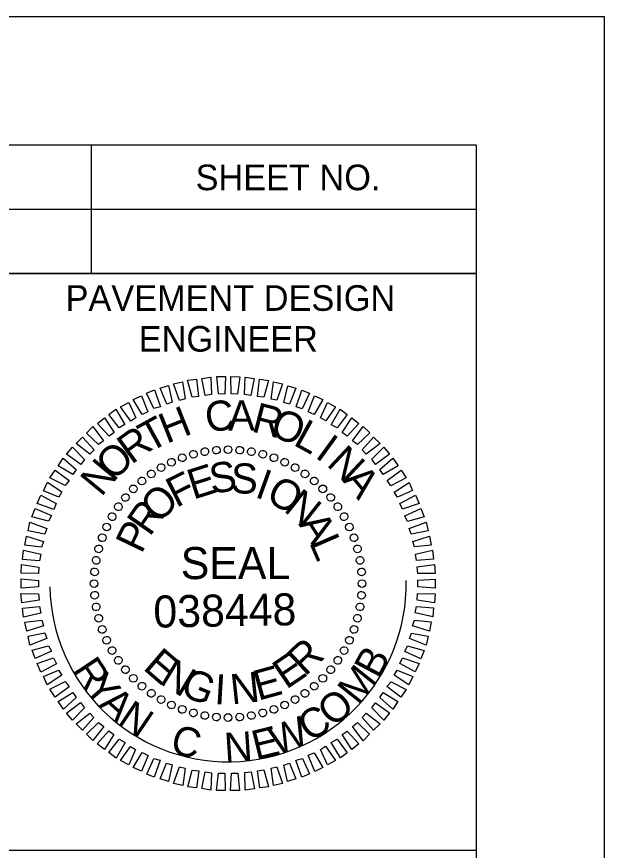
# Model space of a CAD drawing. Extents: x 573078 to 573143.6, y -55221.3 to -55199.3.
# Drawn here: x 573109.723 to 573112.014, y -55202.55 to -55199.298 of the extents above; entities that cross this region are included whole.
import ezdxf

# ---------------------------------------------------------------- set-up
doc = ezdxf.new("R2010")
doc.units = 0
for name, color, linetype in [('Scratch_Level_0', 7, 'Continuous'), ('Scratch_Level_1', 7, 'Continuous'), ('Sheet Plan CELL', 7, 'Continuous'), ('Sheet Plot Border Inside CELL', 7, 'Continuous'), ('Sheet Professional Seal CELL', 7, 'Continuous')]:
    doc.layers.add(name, color=color, linetype=linetype)

msp = doc.modelspace()

# ---------------------------------------------------------------- linework, layer by layer
at = {"layer": 'Scratch_Level_0'}
msp.add_arc((573110.547, -55201.5095), 0.6949, 181, 1, dxfattribs=at)
at = {"layer": 'Scratch_Level_1'}
msp.add_line((573110.547, -55201.5095), (573110.547, -55201.5095), dxfattribs=at)
at = {"layer": 'Sheet Plan CELL'}
for p, q in [((573110.0144, -55200.2999), (573110.0144, -55199.7984)), ((573107.5132, -55200.0494), (573111.5142, -55200.0497))]:
    msp.add_line(p, q, dxfattribs=at)
for points in [[(573081.5142, -55199.7984), (573111.5142, -55199.7984), (573111.5142, -55220.7984), (573081.5142, -55220.7984)], [(573107.5132, -55199.7984), (573111.5142, -55199.7984), (573111.5142, -55200.3002), (573107.5132, -55200.3002)], [(573109.5142, -55200.3002), (573111.5142, -55200.3002), (573111.5142, -55202.5502), (573109.5142, -55202.5502)]]:
    msp.add_lwpolyline(points, close=True, dxfattribs=at)
at = {"layer": 'Sheet Plot Border Inside CELL'}
msp.add_lwpolyline([(573112.0142, -55199.2984), (573078.0142, -55199.2984), (573078.0142, -55221.2984), (573112.0142, -55221.2984)], close=True, dxfattribs=at)
at = {"layer": 'Sheet Professional Seal CELL'}
for p, q in [((573110.4568, -55200.9954), (573110.4568, -55200.9954)), ((573110.5015, -55200.9884), (573110.5015, -55200.9884)), ((573110.5473, -55200.9866), (573110.5473, -55200.9866)), ((573110.5931, -55200.9889), (573110.5931, -55200.9889)), ((573110.638, -55200.9954), (573110.638, -55200.9954)), ((573110.3676, -55201.0178), (573110.3676, -55201.0178)), ((573110.4111, -55201.0046), (573110.4111, -55201.0046)), ((573110.6819, -55201.004), (573110.6819, -55201.004)), ((573110.7259, -55201.0178), (573110.7259, -55201.0178)), ((573110.286, -55201.0568), (573110.286, -55201.0568)), ((573110.3262, -55201.0352), (573110.3262, -55201.0352)), ((573110.7679, -55201.0358), (573110.7679, -55201.0358)), ((573110.8089, -55201.056), (573110.8089, -55201.056)), ((573110.2468, -55201.0814), (573110.2468, -55201.0814)), ((573110.8468, -55201.0813), (573110.8468, -55201.0813)), ((573110.2109, -55201.1081), (573110.2109, -55201.1081)), ((573110.8837, -55201.1088), (573110.8837, -55201.1088)), ((573110.177, -55201.1399), (573110.177, -55201.1399)), ((573110.9166, -55201.1395), (573110.9166, -55201.1395)), ((573110.1464, -55201.1727), (573110.1464, -55201.1727)), ((573110.9484, -55201.1733), (573110.9484, -55201.1733)), ((573110.1189, -55201.2097), (573110.1189, -55201.2097)), ((573110.9751, -55201.2093), (573110.9751, -55201.2093)), ((573110.0935, -55201.2476), (573110.0935, -55201.2476)), ((573110.9997, -55201.2485), (573110.9997, -55201.2485)), ((573110.0734, -55201.2886), (573110.0734, -55201.2886)), ((573111.0212, -55201.2887), (573111.0212, -55201.2887)), ((573110.0554, -55201.3306), (573110.0554, -55201.3306)), ((573111.0386, -55201.3301), (573111.0386, -55201.3301)), ((573110.0416, -55201.3745), (573110.0416, -55201.3745)), ((573111.0519, -55201.3736), (573111.0519, -55201.3736)), ((573110.033, -55201.4184), (573110.033, -55201.4184)), ((573111.061, -55201.4192), (573111.061, -55201.4192)), ((573110.0264, -55201.4633), (573110.0264, -55201.4633)), ((573111.068, -55201.4639), (573111.068, -55201.4639)), ((573110.0241, -55201.5092), (573110.0241, -55201.5092)), ((573110.547, -55201.5095), (573110.547, -55201.5095)), ((573111.0699, -55201.5097), (573111.0699, -55201.5097)), ((573110.026, -55201.555), (573110.026, -55201.555)), ((573111.0676, -55201.5556), (573111.0676, -55201.5556)), ((573110.033, -55201.5997), (573110.033, -55201.5997)), ((573111.0611, -55201.6005), (573111.0611, -55201.6005)), ((573110.0421, -55201.6453), (573110.0421, -55201.6453)), ((573111.0524, -55201.6444), (573111.0524, -55201.6444)), ((573110.0554, -55201.6889), (573110.0554, -55201.6889)), ((573111.0386, -55201.6884), (573111.0386, -55201.6884)), ((573110.0728, -55201.7302), (573110.0728, -55201.7302)), ((573111.0206, -55201.7303), (573111.0206, -55201.7303)), ((573110.0943, -55201.7705), (573110.0943, -55201.7705)), ((573111.0005, -55201.7713), (573111.0005, -55201.7713)), ((573110.1189, -55201.8096), (573110.1189, -55201.8096)), ((573110.9751, -55201.8093), (573110.9751, -55201.8093)), ((573110.1456, -55201.8456), (573110.1456, -55201.8456)), ((573110.9476, -55201.8462), (573110.9476, -55201.8462)), ((573110.1775, -55201.8794), (573110.1775, -55201.8794)), ((573110.917, -55201.879), (573110.917, -55201.879)), ((573110.2103, -55201.9101), (573110.2103, -55201.9101)), ((573110.2472, -55201.9376), (573110.2472, -55201.9376)), ((573110.8472, -55201.9375), (573110.8472, -55201.9375)), ((573110.8832, -55201.9109), (573110.8832, -55201.9109)), ((573110.2852, -55201.963), (573110.2852, -55201.963)), ((573110.808, -55201.9622), (573110.808, -55201.9622)), ((573110.3261, -55201.9831), (573110.3261, -55201.9831)), ((573110.3681, -55202.0011), (573110.3681, -55202.0011)), ((573110.7264, -55202.0011), (573110.7264, -55202.0011)), ((573110.7678, -55201.9837), (573110.7678, -55201.9837)), ((573110.4121, -55202.0149), (573110.4121, -55202.0149)), ((573110.456, -55202.0235), (573110.456, -55202.0235)), ((573110.5009, -55202.03), (573110.5009, -55202.03)), ((573110.5468, -55202.0323), (573110.5468, -55202.0323)), ((573110.5926, -55202.0305), (573110.5926, -55202.0305)), ((573110.6372, -55202.0235), (573110.6372, -55202.0235)), ((573110.6829, -55202.0143), (573110.6829, -55202.0143))]:
    msp.add_line(p, q, dxfattribs=at)
for points in [[(573110.4571, -55200.7757), (573110.4445, -55200.7092), (573110.4798, -55200.7044), (573110.4821, -55200.7721)], [(573110.5091, -55200.7696), (573110.5027, -55200.702), (573110.5371, -55200.7024), (573110.5341, -55200.7702)], [(573110.5591, -55200.7697), (573110.5579, -55200.702), (573110.5923, -55200.7025), (573110.5841, -55200.7703)], [(573110.6112, -55200.7719), (573110.6142, -55200.7042), (573110.6487, -55200.7098), (573110.6363, -55200.7757)], [(573110.3077, -55200.8095), (573110.2827, -55200.7475), (573110.3148, -55200.7375), (573110.3295, -55200.8019)], [(573110.3575, -55200.7951), (573110.3345, -55200.7299), (573110.3697, -55200.722), (573110.3792, -55200.7895)], [(573110.4072, -55200.7828), (573110.3894, -55200.7164), (573110.4237, -55200.7127), (573110.4322, -55200.7792)], [(573110.6613, -55200.7794), (573110.6695, -55200.7126), (573110.704, -55200.7172), (573110.6864, -55200.7821)], [(573110.7146, -55200.7899), (573110.7239, -55200.7221), (573110.7594, -55200.7298), (573110.7366, -55200.7947)], [(573110.7649, -55200.8026), (573110.7794, -55200.7378), (573110.8118, -55200.7476), (573110.7869, -55200.8095)], [(573110.257, -55200.8271), (573110.2289, -55200.7672), (573110.2599, -55200.7541), (573110.2829, -55200.8204)], [(573110.812, -55200.8205), (573110.8348, -55200.7545), (573110.8642, -55200.7665), (573110.8361, -55200.8274)], [(573110.1672, -55200.8755), (573110.1277, -55200.82), (573110.1597, -55200.8027), (573110.1868, -55200.8627)], [(573110.2116, -55200.8497), (573110.1772, -55200.792), (573110.2092, -55200.7769), (573110.2343, -55200.84)], [(573110.8592, -55200.8395), (573110.8842, -55200.7776), (573110.9167, -55200.7916), (573110.8824, -55200.8505)], [(573110.9076, -55200.8626), (573110.9346, -55200.8027), (573110.9662, -55200.8199), (573110.9276, -55200.8747)], [(573110.1219, -55200.9023), (573110.0824, -55200.8499), (573110.1091, -55200.8297), (573110.1445, -55200.8894)], [(573110.9487, -55200.89), (573110.9841, -55200.829), (573111.0115, -55200.8504), (573110.9718, -55200.9021)], [(573110.0828, -55200.9343), (573110.0372, -55200.8851), (573110.0649, -55200.8627), (573110.1024, -55200.9204)], [(573110.9919, -55200.9205), (573111.0294, -55200.8625), (573111.0569, -55200.885), (573111.0119, -55200.9347)], [(573110.0417, -55200.9673), (573109.9951, -55200.9223), (573110.0197, -55200.8968), (573110.0613, -55200.9524)], [(573111.032, -55200.9521), (573111.0738, -55200.8972), (573111.0992, -55200.9217), (573111.0521, -55200.9674)], [(573110.008, -55201.0043), (573109.9542, -55200.9626), (573109.9798, -55200.9382), (573110.0244, -55200.9874)], [(573111.0702, -55200.9879), (573111.1141, -55200.9381), (573111.1395, -55200.9627), (573111.0861, -55201.0043)], [(573109.9723, -55201.0445), (573109.9174, -55201.0049), (573109.9398, -55200.9774), (573109.9865, -55201.0255)], [(573111.1073, -55201.0247), (573111.1543, -55200.977), (573111.1767, -55201.0048), (573111.1222, -55201.0453)], [(573109.9417, -55201.0846), (573109.8849, -55201.0502), (573109.9041, -55201.0197), (573109.9549, -55201.0646)], [(573111.1392, -55201.0648), (573111.1895, -55201.0202), (573111.2098, -55201.05), (573111.152, -55201.0843)], [(573109.9112, -55201.1268), (573109.8524, -55201.0966), (573109.8727, -55201.0671), (573109.9275, -55201.1078)], [(573111.167, -55201.107), (573111.2215, -55201.0665), (573111.2418, -55201.0974), (573111.182, -55201.1276)], [(573109.887, -55201.172), (573109.8272, -55201.1471), (573109.8422, -55201.1145), (573109.8991, -55201.152)], [(573111.1949, -55201.1523), (573111.2526, -55201.1149), (573111.2667, -55201.1469), (573111.2077, -55201.1719)], [(573109.867, -55201.2203), (573109.802, -55201.1975), (573109.8171, -55201.1649), (573109.877, -55201.1972)], [(573111.2165, -55201.1968), (573111.2774, -55201.1644), (573111.2915, -55201.1975), (573111.2273, -55201.2195)], [(573109.847, -55201.2665), (573109.7821, -55201.2489), (573109.7951, -55201.2164), (573109.8581, -55201.2444)], [(573111.2361, -55201.2454), (573111.2991, -55201.2172), (573111.3112, -55201.2493), (573111.2469, -55201.2671)], [(573109.8322, -55201.3167), (573109.7674, -55201.3043), (573109.7741, -55201.2698), (573109.8402, -55201.2947)], [(573111.2536, -55201.2951), (573111.3198, -55201.2699), (573111.3267, -55201.3042), (573111.2613, -55201.3168)], [(573109.8196, -55201.367), (573109.7549, -55201.3598), (573109.7615, -55201.3242), (573109.8275, -55201.3449)], [(573111.267, -55201.3448), (573111.3322, -55201.3239), (573111.3391, -55201.3592), (573111.2736, -55201.3666)], [(573109.8122, -55201.4202), (573109.7454, -55201.4151), (573109.749, -55201.3797), (573109.8169, -55201.3951)], [(573111.2772, -55201.3946), (573111.3447, -55201.3789), (573111.3484, -55201.4142), (573111.2818, -55201.4196)], [(573109.8078, -55201.4703), (573109.7401, -55201.4694), (573109.7416, -55201.435), (573109.8095, -55201.4453)], [(573111.2844, -55201.4445), (573111.3519, -55201.435), (573111.3546, -55201.4704), (573111.2869, -55201.4695)], [(573109.8077, -55201.5224), (573109.7401, -55201.5267), (573109.7395, -55201.4913), (573109.8073, -55201.4974)], [(573111.2863, -55201.4966), (573111.3539, -55201.4922), (573111.3546, -55201.5277), (573111.2867, -55201.5215)], [(573109.8097, -55201.5744), (573109.7421, -55201.5839), (573109.7394, -55201.5486), (573109.8071, -55201.5495)], [(573111.2862, -55201.5486), (573111.3539, -55201.5495), (573111.3524, -55201.5839), (573111.2845, -55201.5737)], [(573109.8168, -55201.6243), (573109.7493, -55201.64), (573109.7456, -55201.6047), (573109.8122, -55201.5994)], [(573111.2818, -55201.5987), (573111.3486, -55201.6038), (573111.345, -55201.6393), (573111.2771, -55201.6238)], [(573109.827, -55201.6741), (573109.7618, -55201.695), (573109.7549, -55201.6597), (573109.8204, -55201.6523)], [(573111.2744, -55201.652), (573111.3391, -55201.6592), (573111.3325, -55201.6947), (573111.2665, -55201.674)], [(573109.8404, -55201.7239), (573109.7742, -55201.749), (573109.7673, -55201.7147), (573109.8327, -55201.7021)], [(573111.2618, -55201.7022), (573111.3266, -55201.7146), (573111.3199, -55201.7491), (573111.2538, -55201.7242)], [(573109.8579, -55201.7736), (573109.7949, -55201.8017), (573109.7829, -55201.7697), (573109.8471, -55201.7519)], [(573111.247, -55201.7524), (573111.3119, -55201.77), (573111.2989, -55201.8026), (573111.236, -55201.7745)], [(573109.8775, -55201.8222), (573109.8166, -55201.8545), (573109.8025, -55201.8214), (573109.8667, -55201.7994)], [(573111.227, -55201.7986), (573111.292, -55201.8214), (573111.2769, -55201.854), (573111.217, -55201.8217)], [(573109.8991, -55201.8666), (573109.8414, -55201.904), (573109.8273, -55201.872), (573109.8863, -55201.847)], [(573111.207, -55201.8469), (573111.2668, -55201.8719), (573111.2518, -55201.9044), (573111.1949, -55201.8669)], [(573109.927, -55201.9119), (573109.8725, -55201.9525), (573109.8522, -55201.9216), (573109.9121, -55201.8913)], [(573111.1828, -55201.8921), (573111.2417, -55201.9223), (573111.2213, -55201.9518), (573111.1665, -55201.9111)], [(573109.9548, -55201.9541), (573109.9046, -55201.9988), (573109.8842, -55201.9689), (573109.942, -55201.9346)], [(573111.1523, -55201.9343), (573111.2091, -55201.9687), (573111.1899, -55201.9992), (573111.1391, -55201.9543)], [(573109.9868, -55201.9942), (573109.9397, -55202.0419), (573109.9173, -55202.0142), (573109.9718, -55201.9736)], [(573111.1217, -55201.9744), (573111.1766, -55202.0141), (573111.1542, -55202.0415), (573111.1075, -55201.9934)], [(573110.0239, -55202.0311), (573109.9799, -55202.0808), (573109.9545, -55202.0562), (573110.0079, -55202.0147)], [(573111.086, -55202.0146), (573111.1398, -55202.0564), (573111.1142, -55202.0808), (573111.0696, -55202.0315)], [(573110.062, -55202.0668), (573110.0202, -55202.1217), (573109.9948, -55202.0972), (573110.0419, -55202.0516)], [(573111.0523, -55202.0516), (573111.0989, -55202.0967), (573111.0743, -55202.1221), (573111.0327, -55202.0666)], [(573110.1021, -55202.0984), (573110.0646, -55202.1564), (573110.0371, -55202.1339), (573110.0821, -55202.0842)], [(573111.0112, -55202.0846), (573111.0568, -55202.1338), (573111.0291, -55202.1562), (573110.9916, -55202.0985)], [(573110.1454, -55202.1289), (573110.11, -55202.19), (573110.0825, -55202.1686), (573110.1222, -55202.1168)], [(573110.9722, -55202.1166), (573111.0116, -55202.169), (573110.9849, -55202.1893), (573110.9495, -55202.1295)], [(573110.1865, -55202.1563), (573110.1594, -55202.2162), (573110.1278, -55202.199), (573110.1664, -55202.1442)], [(573110.2348, -55202.1794), (573110.2098, -55202.2413), (573110.1773, -55202.2273), (573110.2117, -55202.1684)], [(573110.8825, -55202.1692), (573110.9168, -55202.2269), (573110.8848, -55202.242), (573110.8597, -55202.1789)], [(573110.9268, -55202.1434), (573110.9663, -55202.199), (573110.9343, -55202.2162), (573110.9072, -55202.1562)], [(573110.282, -55202.1984), (573110.2592, -55202.2644), (573110.2298, -55202.2524), (573110.2579, -55202.1915)], [(573110.837, -55202.1918), (573110.8651, -55202.2518), (573110.8341, -55202.2648), (573110.8111, -55202.1985)], [(573110.3292, -55202.2163), (573110.3147, -55202.2812), (573110.2822, -55202.2713), (573110.3072, -55202.2094)], [(573110.3794, -55202.229), (573110.3701, -55202.2969), (573110.3346, -55202.2891), (573110.3574, -55202.2242)], [(573110.7365, -55202.2238), (573110.7596, -55202.289), (573110.7243, -55202.2969), (573110.7148, -55202.2294)], [(573110.7863, -55202.2094), (573110.8113, -55202.2715), (573110.7792, -55202.2814), (573110.7645, -55202.2171)], [(573110.4327, -55202.2395), (573110.4245, -55202.3063), (573110.39, -55202.3017), (573110.4076, -55202.2368)], [(573110.4828, -55202.247), (573110.4798, -55202.3147), (573110.4453, -55202.3091), (573110.4577, -55202.2433)], [(573110.5349, -55202.2492), (573110.5361, -55202.3169), (573110.5017, -55202.3164), (573110.5099, -55202.2486)], [(573110.5849, -55202.2494), (573110.5913, -55202.317), (573110.5569, -55202.3165), (573110.5599, -55202.2488)], [(573110.6369, -55202.2433), (573110.6495, -55202.3097), (573110.6142, -55202.3145), (573110.612, -55202.2468)], [(573110.6868, -55202.2361), (573110.7046, -55202.3025), (573110.6703, -55202.3062), (573110.6618, -55202.2397)]]:
    msp.add_lwpolyline(points, close=True, dxfattribs=at)
for centre, major_axis in [((573110.4118, -55201.0049), (-0.0039, 0.0145)), ((573110.4563, -55200.995), (-0.0026, 0.0148)), ((573110.5015, -55200.9891), (-0.0013, 0.0149)), ((573110.547, -55200.9871), (0, 0.015)), ((573110.5925, -55200.9891), (0.0013, 0.0149)), ((573110.6377, -55200.995), (0.0026, 0.0148)), ((573110.6822, -55201.0049), (0.0039, 0.0145)), ((573110.3262, -55201.036), (-0.0063, 0.0136)), ((573110.3683, -55201.0186), (-0.0051, 0.0141)), ((573110.7257, -55201.0186), (0.0051, 0.0141)), ((573110.7678, -55201.036), (0.0063, 0.0136)), ((573110.2858, -55201.0571), (-0.0075, 0.013)), ((573110.8082, -55201.0571), (0.0075, 0.013)), ((573110.2112, -55201.1093), (-0.0096, 0.0115)), ((573110.2474, -55201.0816), (-0.0086, 0.0123)), ((573110.8466, -55201.0816), (0.0086, 0.0123)), ((573110.8828, -55201.1093), (0.0096, 0.0115)), ((573110.1776, -55201.1401), (-0.0106, 0.0106)), ((573110.9164, -55201.1401), (0.0106, 0.0106)), ((573110.1468, -55201.1737), (-0.0115, 0.0096)), ((573110.9472, -55201.1737), (0.0115, 0.0096)), ((573110.1191, -55201.2098), (-0.0123, 0.0086)), ((573110.9749, -55201.2098), (0.0123, 0.0086)), ((573110.0946, -55201.2483), (-0.013, 0.0075)), ((573110.9994, -55201.2483), (0.013, 0.0075)), ((573110.0736, -55201.2887), (-0.0136, 0.0063)), ((573111.0204, -55201.2887), (0.0136, 0.0063)), ((573110.0561, -55201.3308), (-0.0141, 0.0051)), ((573111.0379, -55201.3308), (0.0141, 0.0051)), ((573110.0424, -55201.3743), (-0.0145, 0.0039)), ((573111.0516, -55201.3743), (0.0145, 0.0039)), ((573110.0326, -55201.4187), (-0.0148, 0.0026)), ((573111.0615, -55201.4187), (0.0148, 0.0026)), ((573110.0266, -55201.4639), (-0.0149, 0.0013)), ((573111.0674, -55201.4639), (0.0149, 0.0013)), ((573110.0246, -55201.5095), (-0.015, 0)), ((573111.0694, -55201.5095), (0.015, 0)), ((573110.0266, -55201.555), (-0.0149, -0.0013)), ((573111.0674, -55201.555), (0.0149, -0.0013)), ((573110.0326, -55201.6002), (-0.0148, -0.0026)), ((573111.0615, -55201.6002), (0.0148, -0.0026)), ((573110.0424, -55201.6447), (-0.0145, -0.0039)), ((573111.0516, -55201.6447), (0.0145, -0.0039)), ((573110.0561, -55201.6881), (-0.0141, -0.0051)), ((573111.0379, -55201.6881), (0.0141, -0.0051)), ((573110.0736, -55201.7302), (-0.0136, -0.0063)), ((573111.0204, -55201.7302), (0.0136, -0.0063)), ((573110.0946, -55201.7706), (-0.013, -0.0075)), ((573110.9994, -55201.7706), (0.013, -0.0075)), ((573110.1191, -55201.8091), (-0.0123, -0.0086)), ((573110.9749, -55201.8091), (0.0123, -0.0086)), ((573110.1468, -55201.8452), (-0.0115, -0.0096)), ((573110.9472, -55201.8452), (0.0115, -0.0096)), ((573110.1776, -55201.8788), (-0.0106, -0.0106)), ((573110.9164, -55201.8788), (0.0106, -0.0106)), ((573110.2112, -55201.9096), (-0.0096, -0.0115)), ((573110.8828, -55201.9096), (0.0096, -0.0115)), ((573110.2474, -55201.9374), (-0.0086, -0.0123)), ((573110.8466, -55201.9374), (0.0086, -0.0123)), ((573110.2858, -55201.9619), (-0.0075, -0.013)), ((573110.3262, -55201.9829), (-0.0063, -0.0136)), ((573110.7678, -55201.9829), (0.0063, -0.0136)), ((573110.8082, -55201.9619), (0.0075, -0.013)), ((573110.3683, -55202.0003), (-0.0051, -0.0141)), ((573110.4118, -55202.014), (-0.0039, -0.0145)), ((573110.6822, -55202.014), (0.0039, -0.0145)), ((573110.7257, -55202.0003), (0.0051, -0.0141)), ((573110.4563, -55202.0239), (-0.0026, -0.0148)), ((573110.5015, -55202.0299), (-0.0013, -0.0149)), ((573110.547, -55202.0318), (0, -0.015)), ((573110.5925, -55202.0299), (0.0013, -0.0149)), ((573110.6377, -55202.0239), (0.0026, -0.0148))]:
    msp.add_ellipse(centre, major_axis=major_axis, ratio=0.999708, dxfattribs=at)

# ---------------------------------------------------------------- texts
at = {"layer": 'Sheet Plan CELL'}
for s, height, p in [('SHEET NO.', 0.1, (573110.4204, -55199.9752)), ('PAVEMENT DESIGN', 0.100002, (573109.9133, -55200.4457)), ('ENGINEER', 0.1, (573110.1987, -55200.6049))]:
    msp.add_text(s, height=height, rotation=0, dxfattribs=at).set_placement(p)
at = {"layer": 'Sheet Professional Seal CELL'}
for s, height, rotation, p in [('C', 0.1174, 7.2199, (573110.4649, -55200.9203)), ('A', 0.1174, 0.0203, (573110.547, -55200.9126)), ('H', 0.1174, 21.6195, (573110.3073, -55200.9647)), ('R', 0.1174, 345.6211, (573110.6345, -55200.9153)), ('O', 0.1174, 338.4212, (573110.7046, -55200.9297)), ('T', 0.1174, 28.8198, (573110.2402, -55201.0003)), ('L', 0.1174, 331.2209, (573110.7969, -55200.9666)), ('R', 0.1174, 36.0205, (573110.1702, -55201.0473)), ('I', 0.1174, 324.0201, (573110.8821, -55201.0151)), ('O', 0.1174, 43.2217, (573110.0995, -55201.1131)), ('N', 0.1174, 316.8189, (573110.9274, -55201.0466)), ('N', 0.1174, 50.4235, (573110.0527, -55201.1744)), ('S', 0.1174, 8.2556, (573110.4826, -55201.1596)), ('E', 0.1174, 17.6111, (573110.4111, -55201.1827)), ('S', 0.1174, 358.9004, (573110.5575, -55201.1572)), ('F', 0.1174, 26.967, (573110.345, -55201.2151)), ('I', 0.1174, 340.1896, (573110.6473, -55201.1702)), ('A', 0.1174, 309.6172, (573110.9899, -55201.107)), ('O', 0.1174, 330.8335, (573110.6892, -55201.1841)), ('O', 0.1174, 45.6812, (573110.2774, -55201.2777)), ('N', 0.1174, 321.4766, (573110.7597, -55201.2245)), ('R', 0.1175, 55.0396, (573110.2418, -55201.3294)), ('A', 0.1175, 302.7603, (573110.82, -55201.2776)), ('P', 0.1175, 64.3989, (573110.2096, -55201.3966)), ('L', 0.1175, 293.4008, (573110.8619, -55201.3488)), ('SEAL', 0.12493, 360, (573110.3623, -55201.4919)), ('038448', 0.12493, 1, (573110.2567, -55201.6814)), ('R', 0.1174, 43.4814, (573110.8471, -55201.874)), ('E', 0.1174, 319.2769, (573110.2112, -55201.8413)), ('E', 0.1174, 34.1241, (573110.774, -55201.9242)), ('B', 0.1146, 62.1303, (573111.1346, -55201.8849)), ('R', 0.1146, 303.6223, (573109.9366, -55201.8466)), ('N', 0.1174, 328.634, (573110.2746, -55201.8965)), ('E', 0.1174, 15.4118, (573110.6644, -55201.9668)), ('M', 0.1146, 51.4544, (573111.0548, -55201.9873)), ('Y', 0.1146, 310.5487, (573109.9817, -55201.9177)), ('G', 0.1174, 337.9902, (573110.3546, -55201.942)), ('I', 0.1174, 356.7012, (573110.4917, -55201.9791)), ('N', 0.1174, 6.0564, (573110.5615, -55201.981)), ('A', 0.1146, 317.8759, (573110.0384, -55201.9865)), ('O', 0.1146, 40.7499, (573110.9572, -55202.0733)), ('N', 0.1146, 326.0617, (573110.1115, -55202.054)), ('C', 0.1146, 31.8772, (573110.8654, -55202.1298)), ('W', 0.1146, 20.2711, (573110.734, -55202.1812)), ('C', 0.1146, 345.4385, (573110.3169, -55202.1677)), ('E', 0.1146, 13.6881, (573110.6558, -55202.1982)), ('N', 0.1146, 3.7564, (573110.5354, -55202.2066))]:
    msp.add_text(s, height=height, rotation=rotation, dxfattribs=at).set_placement(p)

doc.saveas('drawing.dxf')
